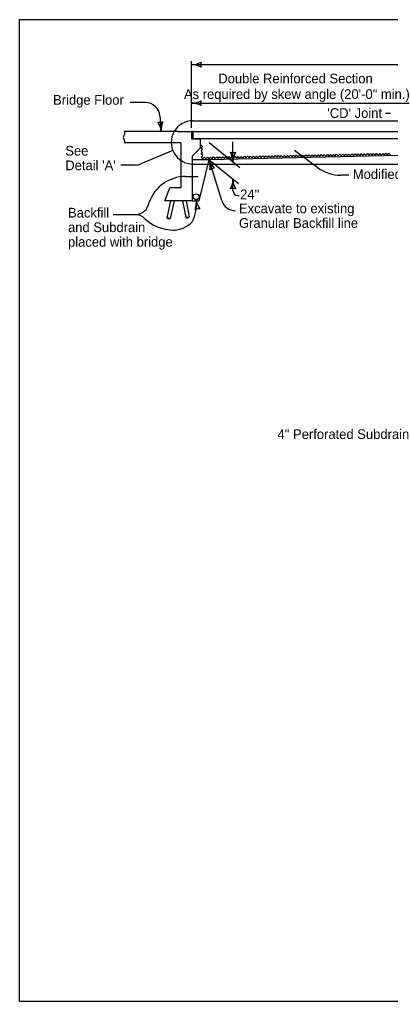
# Model space of a CAD drawing. Extents: x 8925 to 81668, y 4369 to 11918.
# Drawn here: x 13733 to 14496, y 7924 to 9944 of the extents above; entities that cross this region are included whole.
import ezdxf

# ---------------------------------------------------------------- set-up
doc = ezdxf.new("R2010")
doc.units = 0
for name, color, linetype in [('dsnShtPlotShapeBatchPrint', 7, 'Continuous'), ('dsnStdBorder', 7, 'Continuous'), ('Level 3', 7, 'Continuous'), ('SheetBorder', 7, 'Continuous')]:
    doc.layers.add(name, color=color, linetype=linetype)

msp = doc.modelspace()

# ---------------------------------------------------------------- linework, layer by layer
at = {"layer": 'dsnShtPlotShapeBatchPrint'}
for p, q in [((14086.5, 9721.2), (14086.5, 9858.8)), ((14086.5, 9851.4), (15425.9, 9851.4)), ((14086.5, 9772.2), (14534.9, 9772.2)), ((14021.3, 9746.2), (14024.1, 9713.8)), ((14485.7, 9751.8), (14496, 9751.8)), ((14089.4, 9736), (14892.6, 9736)), ((14089.4, 9698.9), (14089.4, 9713.8)), ((14089.4, 9713.8), (14534.9, 9713.8)), ((14104.3, 9698.9), (14089.4, 9698.9)), ((14126.6, 9698.9), (14104.3, 9698.9)), ((14534.9, 9698.9), (14126.6, 9698.9)), ((14123.1, 9691.1), (14185.9, 9640)), ((14171.9, 9651.4), (14171.9, 9692.6)), ((14048.3, 9674.5), (13982.1, 9647.1)), ((14123.1, 9655.8), (14183.3, 9606.8)), ((14148.7, 9571.9), (14123.1, 9655.8)), ((14346.7, 9639.4), (14298.7, 9675)), ((13970.7, 9644.9), (13940.7, 9644.9)), ((14089.4, 9646.9), (14892.6, 9646.9)), ((14074.1, 9621.2), (14099.9, 9621.2)), ((14171.9, 9592.2), (14171.9, 9616.1)), ((14410.7, 9623.8), (14393.9, 9623.8)), ((14181.9, 9582.2), (14184.3, 9582.2)), ((13996.9, 9561.1), (13999.6, 9568.7)), ((13925, 9542.8), (13970.8, 9542.8))]:
    msp.add_line(p, q, dxfattribs=at)
for centre, radius, start, end in [((14089.4, 9691.5), 44.6, 89.9996, 270), ((13970.7, 9674.6), 29.7, 270, 292.4496), ((14393.9, 9703), 79.2, 233.4243, 270), ((14025.5, 9563.1), 71.3, 330.5092, 8.5915), ((14177.1, 9580.5), 29.7, 196.9535, 270), ((14097.2, 9658.2), 163.6, 227.1442, 236.9942), ((14057, 9628.9), 118.5, 245.5915, 265.546), ((14047.5, 9565.7), 55, 270.3325, 316.7198)]:
    msp.add_arc(centre, radius, start, end, dxfattribs=at)
at = {"layer": 'dsnStdBorder'}
for p, q in [((13992.2, 9773.4), (13960.4, 9773.4)), ((14058.2, 9713.8), (13947.6, 9713.8)), ((14058.2, 9713.8), (14086.5, 9713.8)), ((14086.5, 9713.8), (14086.5, 9698.8)), ((14089.4, 9713.8), (14086.5, 9713.8)), ((14086.5, 9712.5), (14087.3, 9713.3)), ((14086.5, 9710.4), (14089.4, 9713.3)), ((14089.4, 9713.3), (14086.5, 9713.3)), ((14086.5, 9708.3), (14089.4, 9711.2)), ((14086.5, 9706.2), (14089.4, 9709.1)), ((14086.5, 9704.1), (14089.4, 9707)), ((14086.5, 9702), (14089.4, 9704.9)), ((14086.5, 9699.9), (14089.4, 9702.8)), ((14086.5, 9698.8), (14104.3, 9698.8)), ((14087.5, 9698.8), (14089.4, 9700.7)), ((14089.4, 9713.8), (14089.4, 9698.8)), ((14089.4, 9713.8), (15244.3, 9713.8)), ((15230.7, 9698.9), (14089.4, 9698.9)), ((14126.6, 9698.9), (14103.3, 9698.9)), ((14104.3, 9698.9), (14104.3, 9679.6)), ((14064.2, 9690.8), (13947.6, 9690.8)), ((14064.2, 9690.8), (14064.2, 9597.9)), ((14104.3, 9679.6), (14087.5, 9662.8)), ((15240.3, 9681.1), (14123.1, 9655.8)), ((14087.5, 9662.8), (14087.5, 9571.2)), ((14123.1, 9655.8), (14087.5, 9655.8)), ((14102.4, 9571.2), (14123.1, 9655.8)), ((14031.5, 9571.2), (14041.8, 9597.9)), ((14064.2, 9597.9), (14041.8, 9597.9)), ((14087.5, 9571.2), (14031.5, 9571.2)), ((14043, 9571.2), (14035.5, 9536.4)), ((14050.6, 9571.2), (14042.7, 9534.8)), ((14068.2, 9571.2), (14074.5, 9536.9)), ((14075.8, 9571.2), (14081.9, 9538.2)), ((14087.5, 9571.2), (14102.4, 9571.2))]:
    msp.add_line(p, q, dxfattribs=at)
for points in [[(14108.2, 9659.4), (14106.5, 9661.1), (14109.6, 9664.3), (14106.3, 9667.4), (14109.4, 9670.6), (14106.2, 9673.7), (14109.3, 9677), (14106.1, 9680.1), (14109.1, 9683.3), (14105.9, 9686.4), (14106.1, 9686.5)], [(14106.6, 9660.9), (14106.6, 9660.9), (14109.9, 9657.8), (14113, 9661.1), (14116.2, 9658), (14119.3, 9661.2), (14122.5, 9658.1), (14125.6, 9661.3), (14128.9, 9658.2), (14132, 9661.5), (14135.2, 9658.4), (14138.3, 9661.6), (14141.5, 9658.5), (14144.6, 9661.8), (14147.9, 9658.7), (14151, 9661.9), (14154.2, 9658.8), (14157.3, 9662), (14160.5, 9658.9), (14163.6, 9662.2), (14165.3, 9660.6)], [(14165.3, 9660.6), (14166.9, 9659.1), (14170, 9662.3), (14173.2, 9659.2), (14176.3, 9662.4), (14179.5, 9659.3), (14182.6, 9662.6), (14185.9, 9659.5), (14189, 9662.7), (14192.2, 9659.6), (14195.3, 9662.8), (14198.5, 9659.7), (14201.6, 9663), (14204.9, 9659.9), (14208, 9663.1), (14211.2, 9660), (14214.3, 9663.2), (14217.5, 9660.1), (14220.6, 9663.4), (14223.9, 9660.3), (14227, 9663.5), (14230.2, 9660.4), (14233.3, 9663.6), (14236.6, 9660.6), (14239.7, 9663.8), (14241.3, 9662.2)], [(14241.3, 9662.2), (14242.9, 9660.7), (14246, 9663.9), (14249.2, 9660.8), (14252.3, 9664.1), (14255.6, 9661), (14258.7, 9664.2), (14261.9, 9661.1), (14265, 9664.3), (14268.2, 9661.2), (14271.3, 9664.5), (14274.6, 9661.4), (14277.7, 9664.6), (14280.9, 9661.5), (14284, 9664.7), (14287.2, 9661.6), (14290.3, 9664.9), (14293.6, 9661.8), (14296.7, 9665), (14299.9, 9661.9), (14303, 9665.1), (14306.2, 9662), (14309.3, 9665.3), (14312.6, 9662.2), (14315.7, 9665.4), (14317.3, 9663.9)], [(14317.3, 9663.9), (14318.9, 9662.3), (14322, 9665.5), (14325.2, 9662.4), (14328.3, 9665.7), (14331.6, 9662.6), (14334.7, 9665.8), (14337.9, 9662.7), (14341, 9666), (14344.2, 9662.9), (14347.3, 9666.1), (14350.6, 9663), (14353.7, 9666.2), (14356.9, 9663.1), (14360, 9666.4), (14363.2, 9663.3), (14366.3, 9666.5), (14369.6, 9663.4), (14372.7, 9666.6), (14375.9, 9663.5), (14379, 9666.8), (14382.2, 9663.7), (14385.3, 9666.9), (14388.6, 9663.8), (14391.7, 9667), (14393.3, 9665.5)], [(14393.3, 9665.5), (14394.9, 9663.9), (14398, 9667.2), (14401.3, 9664.1), (14404.3, 9667.3), (14407.6, 9664.2), (14410.7, 9667.4), (14413.9, 9664.3), (14417, 9667.6), (14420.3, 9664.5), (14423.4, 9667.7), (14426.6, 9664.6), (14429.7, 9667.9), (14432.9, 9664.7), (14436, 9668), (14439.3, 9664.9), (14442.4, 9668.1), (14445.6, 9665), (14448.7, 9668.3), (14451.9, 9665.2), (14455, 9668.4), (14458.3, 9665.3), (14461.4, 9668.5), (14464.6, 9665.4), (14467.7, 9668.7), (14469.3, 9667.1)], [(14469.3, 9667.1), (14470.9, 9665.6), (14474, 9668.8), (14477.3, 9665.7), (14480.4, 9668.9), (14483.6, 9665.8), (14486.7, 9669.1), (14489.9, 9666), (14493, 9669.2), (14496.3, 9666.1)]]:
    msp.add_lwpolyline(points, dxfattribs=at)
msp.add_circle((14096, 9579.7), 5.94, dxfattribs=at)
for centre, radius, start, end in [((13991.7, 9743.7), 29.7, 4.9696, 89.1065), ((14171.9, 9687.2), 16.5, 252.2666, 287.7333), ((14129.1, 9651.4), 42.7, 360, 28.0725), ((14171.9, 9687.2), 16.5, 252.2666, 287.7333), ((14129.1, 9651.4), 42.7, 360, 28.0725), ((14214.6, 9651.4), 42.7, 151.9275, 180), ((14214.6, 9651.4), 42.7, 151.9275, 180), ((14074.1, 9542), 79.2, 90, 160.3012), ((14181.9, 9592.2), 10, 180, 270), ((13970.8, 9570.5), 27.7, 270, 340.3019), ((13970.8, 9515), 27.7, 56.8248, 90)]:
    msp.add_arc(centre, radius, start, end, dxfattribs=at)
for points in [[(13947.6, 9713.8), (13948.8, 9707.8), (13945.8, 9701.8), (13948.6, 9694.2), (13948.1, 9690.8)], [(14035.5, 9536.4), (14038.6, 9536.7), (14040.3, 9535), (14042.7, 9534.8)], [(14035.5, 9536.4), (14037.6, 9534.9), (14040, 9535.1)], [(14074.5, 9536.9), (14077.3, 9538), (14080.1, 9536.8), (14081.9, 9538.2)], [(14074.5, 9536.9), (14077.3, 9535.9), (14079.3, 9536.8)]]:
    msp.add_spline(points, degree=3, dxfattribs=at)
at = {"layer": 'Level 3'}
for centre, radius, start, end in [((14086.5, 9893.9), 42.5, 270, 298.0725), ((14086.5, 9808.9), 42.5, 61.9275, 90), ((14122.1, 9851.4), 16.4, 162.2666, 197.7334), ((14086.5, 9814.7), 42.5, 270, 298.0725), ((14122.1, 9772.2), 16.4, 162.2666, 197.7334), ((14086.5, 9729.7), 42.5, 61.9275, 90), ((14021, 9749.3), 16.4, 257.2333, 292.7), ((13981.8, 9710.1), 42.5, 4.9667, 33.0392), ((14066.5, 9717.4), 42.5, 156.8942, 184.9667), ((14163.7, 9668.2), 42.5, 196.9516, 225.0241), ((14082.4, 9643.4), 42.5, 348.8791, 16.9516), ((14133.5, 9621.7), 16.4, 89.2182, 124.6849), ((14129.4, 9616.1), 42.5, 331.9275, 360), ((14214.4, 9616.1), 42.5, 180, 208.0725), ((14171.9, 9580.4), 16.4, 72.2666, 107.7334), ((14054, 9567.4), 42.5, 340.519, 8.5915), ((14101.3, 9538.5), 16.4, 80.8581, 116.3248), ((14138, 9580.1), 42.5, 188.5915, 216.6639)]:
    msp.add_arc(centre, radius, start, end, dxfattribs=at)
at = {"layer": 'SheetBorder'}
msp.add_lwpolyline([(13732.5, 9944), (16867.5, 9944), (16867.5, 7924), (13732.5, 7924)], close=True, dxfattribs=at)

# ---------------------------------------------------------------- texts
at = {"layer": 'dsnShtPlotShapeBatchPrint'}
for s, p in [('Double Reinforced Section', (14141.6, 9812.9)), ('As required by skew angle (20\'-0" min.)', (14070.9, 9780.8)), ('Bridge Floor', (13801.4, 9768.9)), ("'CD' Joint", (14366.1, 9741.8)), ('See', (13826.6, 9664.2)), ("Detail 'A'", (13826.6, 9634.2)), ('Modified Subbase', (14418.6, 9616.1)), ('24"', (14186.6, 9574.5)), ('Backfill', (13832.2, 9536.8)), ('Excavate to existing', (14184.2, 9545.6)), ('Granular Backfill line', (14184.2, 9515.6)), ('and Subdrain', (13832.2, 9506.8)), ('placed with bridge', (13832.2, 9476.8)), ('4" Perforated Subdrain', (14263.7, 9081.1))]:
    msp.add_text(s, height=20, dxfattribs=at).set_placement(p)

doc.saveas('drawing.dxf')
